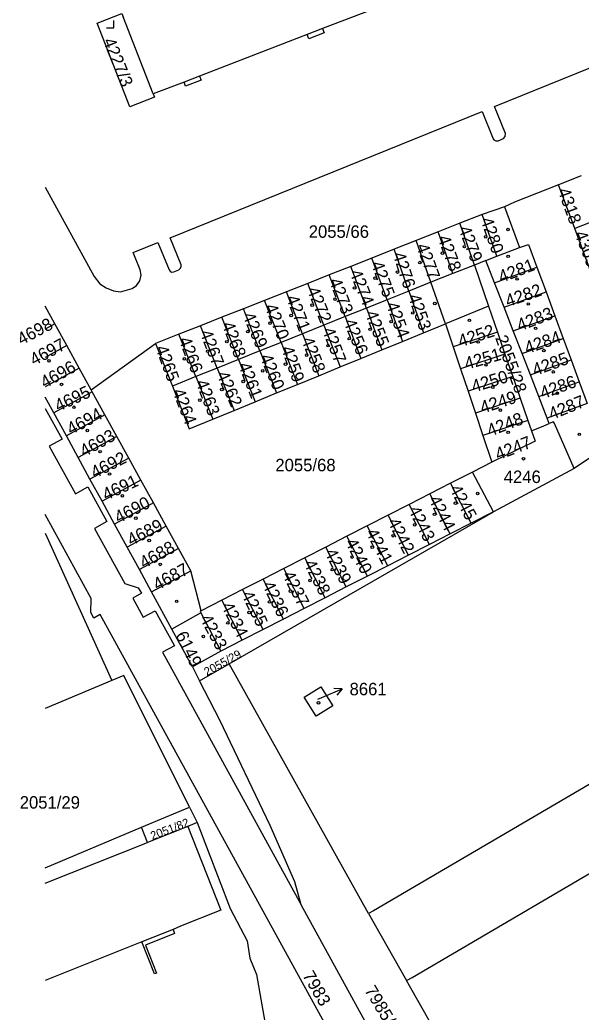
# Model space of a CAD drawing. Extents: x -564952 to -564307, y -1202373 to -1201847.
# Drawn here: x -564948.9 to -564872.3, y -1202052.1 to -1201916.7 of the extents above; entities that cross this region are included whole.
import ezdxf

# ---------------------------------------------------------------- set-up
doc = ezdxf.new("R2010")
doc.units = 0
for name, color, linetype in [('Hranice parcel', 7, 'Continuous'), ('Parcelní čísla', 7, 'Continuous'), ('Pop  PČ popisy', 7, 'Continuous'), ('Vnitřní kresba', 7, 'Continuous'), ('Značky budov', 7, 'Continuous'), ('Značky kultur', 7, 'Continuous')]:
    doc.layers.add(name, color=color, linetype=linetype)

msp = doc.modelspace()

# ---------------------------------------------------------------- linework, layer by layer
at = {"layer": 'Hranice parcel'}
for p, q in [((-564930.69, -1201926.82), (-564934.81, -1201916.29)), ((-564872.31, -1201938.01), (-564875.4, -1201939.21)), ((-564873.18, -1201945.18), (-564875.4, -1201939.21)), ((-564882.78, -1201942.21), (-564885.84, -1201943.28)), ((-564882.78, -1201942.21), (-564880.74, -1201947.76)), ((-564885.84, -1201943.28), (-564888.86, -1201944.47)), ((-564883.83, -1201948.97), (-564885.84, -1201943.28)), ((-564870.03, -1201943.94), (-564873.18, -1201945.18)), ((-564891.84, -1201945.65), (-564894.82, -1201946.82)), ((-564888.86, -1201944.47), (-564891.84, -1201945.65)), ((-564889.83, -1201951.33), (-564891.84, -1201945.65)), ((-564886.86, -1201950.16), (-564888.86, -1201944.47)), ((-564894.82, -1201946.82), (-564897.84, -1201948.02)), ((-564892.81, -1201952.5), (-564894.82, -1201946.82)), ((-564897.84, -1201948.02), (-564900.86, -1201949.21)), ((-564895.83, -1201953.72), (-564897.84, -1201948.02)), ((-564883.83, -1201948.97), (-564880.74, -1201947.76)), ((-564900.86, -1201949.21), (-564903.74, -1201950.35)), ((-564898.78, -1201954.9), (-564900.86, -1201949.21)), ((-564885.3, -1201949.55), (-564886.86, -1201950.16)), ((-564885.3, -1201949.55), (-564883.83, -1201948.97)), ((-564884.12, -1201952.6), (-564885.3, -1201949.55)), ((-564903.74, -1201950.35), (-564906.67, -1201951.51)), ((-564901.62, -1201956.04), (-564903.74, -1201950.35)), ((-564886.86, -1201950.16), (-564889.83, -1201951.33)), ((-564886.86, -1201950.16), (-564884.94, -1201955.77)), ((-564884.12, -1201952.6), (-564878.35, -1201950.46)), ((-564878.35, -1201950.46), (-564877.1, -1201953.83)), ((-564906.67, -1201951.51), (-564909.6, -1201952.66)), ((-564904.52, -1201957.2), (-564906.67, -1201951.51)), ((-564892.81, -1201952.5), (-564895.83, -1201953.72)), ((-564889.83, -1201951.33), (-564892.81, -1201952.5)), ((-564912.53, -1201953.82), (-564915.51, -1201954.99)), ((-564909.6, -1201952.66), (-564912.53, -1201953.82)), ((-564910.32, -1201959.53), (-564912.53, -1201953.82)), ((-564907.41, -1201958.36), (-564909.6, -1201952.66)), ((-564895.83, -1201953.72), (-564898.78, -1201954.9)), ((-564895.83, -1201953.72), (-564893.83, -1201959.41)), ((-564882.83, -1201955.93), (-564884.12, -1201952.6)), ((-564882.83, -1201955.93), (-564877.1, -1201953.83)), ((-564877.1, -1201953.83), (-564875.91, -1201957.07)), ((-564915.51, -1201954.99), (-564918.39, -1201956.13)), ((-564913.26, -1201960.71), (-564915.51, -1201954.99)), ((-564898.78, -1201954.9), (-564901.62, -1201956.04)), ((-564898.78, -1201954.9), (-564896.7, -1201960.58)), ((-564944.12, -1201958.18), (-564945.44, -1201955.78)), ((-564918.39, -1201956.13), (-564921.32, -1201957.29)), ((-564916.13, -1201961.87), (-564918.39, -1201956.13)), ((-564901.62, -1201956.04), (-564904.52, -1201957.2)), ((-564901.62, -1201956.04), (-564899.5, -1201961.73)), ((-564884.94, -1201955.77), (-564890.81, -1201958.17)), ((-564884.94, -1201955.77), (-564883.73, -1201959.31)), ((-564881.58, -1201959.15), (-564882.83, -1201955.93)), ((-564921.32, -1201957.29), (-564924.25, -1201958.45)), ((-564919.05, -1201963.04), (-564921.32, -1201957.29)), ((-564904.52, -1201957.2), (-564907.41, -1201958.36)), ((-564904.52, -1201957.2), (-564902.36, -1201962.9)), ((-564881.58, -1201959.15), (-564875.91, -1201957.07)), ((-564875.91, -1201957.07), (-564874.77, -1201960.17)), ((-564944.12, -1201958.18), (-564945.44, -1201958.91)), ((-564942.49, -1201961.14), (-564944.12, -1201958.18)), ((-564924.25, -1201958.45), (-564927.18, -1201959.6)), ((-564921.95, -1201964.21), (-564924.25, -1201958.45)), ((-564907.41, -1201958.36), (-564910.32, -1201959.53)), ((-564907.41, -1201958.36), (-564905.21, -1201964.06)), ((-564893.83, -1201959.41), (-564890.81, -1201958.17)), ((-564890.81, -1201958.17), (-564889.76, -1201961.32)), ((-564880.38, -1201962.23), (-564881.58, -1201959.15)), ((-564927.18, -1201959.6), (-564930.39, -1201960.87)), ((-564924.87, -1201965.38), (-564927.18, -1201959.6)), ((-564910.32, -1201959.53), (-564913.26, -1201960.71)), ((-564910.32, -1201959.53), (-564908.11, -1201965.25)), ((-564899.5, -1201961.73), (-564896.7, -1201960.58)), ((-564896.7, -1201960.58), (-564893.83, -1201959.41)), ((-564883.73, -1201959.31), (-564889.76, -1201961.32)), ((-564883.73, -1201959.31), (-564882.71, -1201962.3)), ((-564880.38, -1201962.23), (-564874.77, -1201960.17)), ((-564874.77, -1201960.17), (-564873.7, -1201963.08)), ((-564942.49, -1201961.14), (-564945.44, -1201962.77)), ((-564940.79, -1201964.23), (-564942.49, -1201961.14)), ((-564939.17, -1201967.16), (-564930.39, -1201960.87)), ((-564930.39, -1201960.87), (-564928.08, -1201966.67)), ((-564916.13, -1201961.87), (-564919.05, -1201963.04)), ((-564913.26, -1201960.71), (-564916.13, -1201961.87)), ((-564916.13, -1201961.87), (-564913.87, -1201967.61)), ((-564913.26, -1201960.71), (-564911, -1201966.44)), ((-564902.36, -1201962.9), (-564899.5, -1201961.73)), ((-564889.76, -1201961.32), (-564888.76, -1201964.32)), ((-564919.05, -1201963.04), (-564921.95, -1201964.21)), ((-564919.05, -1201963.04), (-564916.78, -1201968.8)), ((-564905.21, -1201964.06), (-564902.36, -1201962.9)), ((-564882.71, -1201962.3), (-564888.76, -1201964.32)), ((-564882.71, -1201962.3), (-564881.66, -1201965.35)), ((-564879.25, -1201965.13), (-564880.38, -1201962.23)), ((-564879.25, -1201965.13), (-564873.7, -1201963.08)), ((-564873.7, -1201963.08), (-564872.59, -1201966.08)), ((-564940.79, -1201964.23), (-564945.44, -1201966.79)), ((-564939.17, -1201967.16), (-564940.79, -1201964.23)), ((-564921.95, -1201964.21), (-564924.87, -1201965.38)), ((-564921.95, -1201964.21), (-564919.65, -1201969.98)), ((-564908.11, -1201965.25), (-564905.21, -1201964.06)), ((-564888.76, -1201964.32), (-564887.74, -1201967.37)), ((-564924.87, -1201965.38), (-564928.08, -1201966.67)), ((-564924.87, -1201965.38), (-564922.55, -1201971.16)), ((-564911, -1201966.44), (-564908.11, -1201965.25)), ((-564881.66, -1201965.35), (-564887.74, -1201967.37)), ((-564881.66, -1201965.35), (-564880.63, -1201968.34)), ((-564878.1, -1201968.11), (-564879.25, -1201965.13)), ((-564939.01, -1201967.45), (-564939.17, -1201967.16)), ((-564913.87, -1201967.61), (-564911, -1201966.44)), ((-564887.74, -1201967.37), (-564886.74, -1201970.38)), ((-564878.1, -1201968.11), (-564872.59, -1201966.08)), ((-564872.59, -1201966.08), (-564871.5, -1201969.04)), ((-564944.25, -1201970.33), (-564945.44, -1201968.16)), ((-564939.01, -1201967.45), (-564944.25, -1201970.33)), ((-564937.28, -1201970.59), (-564939.01, -1201967.45)), ((-564916.78, -1201968.8), (-564913.87, -1201967.61)), ((-564880.63, -1201968.34), (-564886.74, -1201970.38)), ((-564880.63, -1201968.34), (-564879.59, -1201971.35)), ((-564876.96, -1201971.05), (-564878.1, -1201968.11)), ((-564922.55, -1201971.16), (-564919.65, -1201969.98)), ((-564919.65, -1201969.98), (-564916.78, -1201968.8)), ((-564871.5, -1201969.04), (-564876.96, -1201971.05)), ((-564942.54, -1201973.47), (-564944.25, -1201970.33)), ((-564937.28, -1201970.59), (-564942.54, -1201973.47)), ((-564935.65, -1201973.56), (-564937.28, -1201970.59)), ((-564886.74, -1201970.38), (-564885.73, -1201973.4)), ((-564879.59, -1201971.35), (-564885.73, -1201973.4)), ((-564879.59, -1201971.35), (-564879.09, -1201972.79)), ((-564940.92, -1201976.43), (-564942.54, -1201973.47)), ((-564935.65, -1201973.56), (-564940.92, -1201976.43)), ((-564934.03, -1201976.49), (-564935.65, -1201973.56)), ((-564885.73, -1201973.4), (-564884.51, -1201977.05)), ((-564939.32, -1201979.36), (-564940.92, -1201976.43)), ((-564934.03, -1201976.49), (-564939.32, -1201979.36)), ((-564932.37, -1201979.51), (-564934.03, -1201976.49)), ((-564884.51, -1201977.05), (-564887.14, -1201978.39)), ((-564937.67, -1201982.37), (-564939.32, -1201979.36)), ((-564932.37, -1201979.51), (-564937.67, -1201982.37)), ((-564930.66, -1201982.6), (-564932.37, -1201979.51)), ((-564887.14, -1201978.39), (-564890.13, -1201979.92)), ((-564884.28, -1201983.8), (-564887.14, -1201978.39)), ((-564890.13, -1201979.92), (-564892.98, -1201981.38)), ((-564887.34, -1201985.37), (-564890.13, -1201979.92)), ((-564892.98, -1201981.38), (-564895.78, -1201982.81)), ((-564890.2, -1201986.83), (-564892.98, -1201981.38)), ((-564935.97, -1201985.49), (-564937.67, -1201982.37)), ((-564930.66, -1201982.6), (-564935.97, -1201985.49)), ((-564928.92, -1201985.76), (-564930.66, -1201982.6)), ((-564895.78, -1201982.81), (-564898.65, -1201984.28)), ((-564892.99, -1201988.26), (-564895.78, -1201982.81)), ((-564920.35, -1202004.55), (-564884.28, -1201983.8)), ((-564898.65, -1201984.28), (-564901.49, -1201985.73)), ((-564895.87, -1201989.73), (-564898.65, -1201984.28)), ((-564884.28, -1201983.8), (-564887.34, -1201985.37)), ((-564934.26, -1201988.62), (-564935.97, -1201985.49)), ((-564928.92, -1201985.76), (-564934.26, -1201988.62)), ((-564927.23, -1201988.84), (-564928.92, -1201985.76)), ((-564901.49, -1201985.73), (-564904.28, -1201987.15)), ((-564898.71, -1201991.18), (-564901.49, -1201985.73)), ((-564887.34, -1201985.37), (-564890.2, -1201986.83)), ((-564945.44, -1201986.74), (-564936.35, -1202006.83)), ((-564904.28, -1201987.15), (-564907.15, -1201988.63)), ((-564901.47, -1201992.59), (-564904.28, -1201987.15)), ((-564890.2, -1201986.83), (-564892.99, -1201988.26)), ((-564932.58, -1201991.7), (-564934.26, -1201988.62)), ((-564927.23, -1201988.84), (-564932.58, -1201991.7)), ((-564925.56, -1201991.86), (-564927.23, -1201988.84)), ((-564907.15, -1201988.63), (-564910.03, -1201990.1)), ((-564904.37, -1201994.07), (-564907.15, -1201988.63)), ((-564892.99, -1201988.26), (-564895.87, -1201989.73)), ((-564910.03, -1201990.1), (-564912.87, -1201991.55)), ((-564907.25, -1201995.54), (-564910.03, -1201990.1)), ((-564895.87, -1201989.73), (-564898.71, -1201991.18)), ((-564930.93, -1201994.72), (-564932.58, -1201991.7)), ((-564912.87, -1201991.55), (-564915.7, -1201993)), ((-564910.08, -1201996.99), (-564912.87, -1201991.55)), ((-564898.71, -1201991.18), (-564901.47, -1201992.59)), ((-564930.93, -1201994.72), (-564925.56, -1201991.86)), ((-564924.16, -1201997.32), (-564925.56, -1201991.86)), ((-564915.7, -1201993), (-564918.49, -1201994.42)), ((-564912.93, -1201998.45), (-564915.7, -1201993)), ((-564901.47, -1201992.59), (-564904.37, -1201994.07)), ((-564918.49, -1201994.42), (-564921.32, -1201995.87)), ((-564915.7, -1201999.87), (-564918.49, -1201994.42)), ((-564904.37, -1201994.07), (-564907.25, -1201995.54)), ((-564907.25, -1201995.54), (-564910.08, -1201996.99)), ((-564921.32, -1201995.87), (-564924.16, -1201997.32)), ((-564918.54, -1202001.32), (-564921.32, -1201995.87)), ((-564910.08, -1201996.99), (-564912.93, -1201998.45)), ((-564907.33, -1202053.49), (-564937.93, -1201997.84)), ((-564912.93, -1201998.45), (-564915.7, -1201999.87)), ((-564915.7, -1201999.87), (-564918.54, -1202001.32)), ((-564918.54, -1202001.32), (-564921.45, -1202002.81)), ((-564929.44, -1202002.95), (-564910.5, -1202037.44)), ((-564921.45, -1202002.81), (-564925.31, -1202004.98)), ((-564925.31, -1202004.98), (-564924.36, -1202006.85)), ((-564924.36, -1202006.85), (-564920.35, -1202004.55)), ((-564901.31, -1202038.62), (-564920.35, -1202004.55)), ((-564936.35, -1202006.83), (-564945.44, -1202010.66)), ((-564921.61, -1202012.25), (-564924.36, -1202006.85)), ((-564932.27, -1202026.82), (-564925.74, -1202024.08)), ((-564925.74, -1202024.08), (-564924.68, -1202026.21)), ((-564945.44, -1202032.36), (-564932.27, -1202026.82)), ((-564931.46, -1202028.91), (-564932.27, -1202026.82)), ((-564925.98, -1202026.73), (-564931.46, -1202028.91)), ((-564924.68, -1202026.21), (-564925.98, -1202026.73)), ((-564910.5, -1202037.44), (-564911.38, -1202034.28)), ((-564890.53, -1202073.8), (-564910.5, -1202037.44)), ((-564900.66, -1202038.24), (-564901.31, -1202038.62)), ((-564901.31, -1202038.62), (-564896.13, -1202047.75)), ((-564896.13, -1202047.75), (-564895.38, -1202047.31))]:
    msp.add_line(p, q, dxfattribs=at)
for points in [[(-564896.69, -1201913.72), (-564907.6, -1201917.92), (-564907.38, -1201918.49), (-564909.48, -1201919.31), (-564909.7, -1201918.73), (-564913.71, -1201920.28), (-564924.39, -1201924.39), (-564924.16, -1201924.97), (-564926.27, -1201925.78), (-564926.49, -1201925.2), (-564930.69, -1201926.82)], [(-564945.44, -1201939.52), (-564938.76, -1201951.71), (-564937.99, -1201952.71), (-564937.12, -1201953.29), (-564936.13, -1201953.66), (-564935.14, -1201953.8), (-564933.55, -1201953.37), (-564932.96, -1201952.94), (-564932.5, -1201952.33), (-564932.35, -1201951.55), (-564932.48, -1201950.82), (-564933.42, -1201948.47), (-564930.04, -1201947.09), (-564928.52, -1201950.82), (-564928.4, -1201950.99), (-564928.19, -1201951.14), (-564927.89, -1201951.1), (-564927.18, -1201950.81), (-564926.96, -1201950.61), (-564926.86, -1201950.34), (-564926.9, -1201950.15), (-564928.37, -1201946.43), (-564885.83, -1201929.22), (-564884.32, -1201932.93), (-564884.21, -1201933.08), (-564883.97, -1201933.22), (-564883.66, -1201933.21), (-564882.92, -1201932.91), (-564882.69, -1201932.64), (-564882.65, -1201932.23), (-564884.14, -1201928.55), (-564852.58, -1201915.77)], [(-564930.69, -1201926.82), (-564930.52, -1201927.26), (-564933.89, -1201928.57), (-564938.33, -1201917.16), (-564934.98, -1201915.86), (-564934.81, -1201916.29)], [(-564875.4, -1201939.21), (-564881.39, -1201941.61), (-564882.78, -1201942.21)], [(-564867.83, -1201949.67), (-564871.04, -1201950.95), (-564873.18, -1201945.18)], [(-564880.74, -1201947.76), (-564879.49, -1201947.36), (-564878.35, -1201950.46)], [(-564779.51, -1201950.78), (-564772.34, -1201963.08), (-564900.66, -1202038.24)], [(-564928.08, -1201966.67), (-564925.77, -1201972.48), (-564922.55, -1201971.16)], [(-564945.44, -1201969.73), (-564943.13, -1201973.9), (-564944.9, -1201974.88), (-564941.31, -1201981.37), (-564939.59, -1201980.42), (-564937, -1201985.15), (-564938.7, -1201986.1), (-564934.55, -1201993.61), (-564932.76, -1201994.17), (-564932.3, -1201994.93), (-564933.45, -1201995.59), (-564932.06, -1201998.2), (-564930.43, -1201997.3), (-564927.81, -1202002.08), (-564929.44, -1202002.95)], [(-564879.09, -1201972.79), (-564877.42, -1201972.1), (-564876.67, -1201971.79), (-564876.96, -1201971.05)], [(-564879.09, -1201972.79), (-564878.61, -1201974.17), (-564878.87, -1201974.3), (-564884.16, -1201976.87), (-564884.51, -1201977.05)], [(-564868.52, -1201974.75), (-564873.28, -1201977.89), (-564884.28, -1201983.8)], [(-564939.14, -1201995.62), (-564945.44, -1201984.18)], [(-564937.93, -1201997.84), (-564938.79, -1201998.31), (-564939.22, -1201997.55), (-564939.14, -1201995.62)], [(-564925.31, -1202004.98), (-564928.13, -1201999.83), (-564930.93, -1201994.72)], [(-564924.16, -1201997.32), (-564924.29, -1201997.39), (-564924.19, -1201997.59), (-564921.45, -1202002.81)], [(-564925.74, -1202024.08), (-564934.68, -1202006.12), (-564936.35, -1202006.83)], [(-564906.21, -1202010.26), (-564908.47, -1202011.67), (-564910.1, -1202009.09), (-564907.84, -1202007.68), (-564906.21, -1202010.26)], [(-564911.38, -1202034.28), (-564914.76, -1202026.6), (-564921.61, -1202012.25)], [(-564895.38, -1202047.31), (-564863.11, -1202028.42), (-564854.46, -1202023.35), (-564835.41, -1202055.88), (-564874.17, -1202078.58)], [(-564925.98, -1202026.73), (-564921.46, -1202038.16), (-564926.95, -1202040.34), (-564927.99, -1202040.76), (-564927.77, -1202041.31), (-564931.76, -1202042.91), (-564930.24, -1202046.72), (-564930.52, -1202046.83), (-564932.26, -1202042.46), (-564945.44, -1202047.72)], [(-564924.68, -1202026.21), (-564920.18, -1202037.93), (-564917.87, -1202042.31), (-564917.51, -1202044.68), (-564916.61, -1202046.93), (-564913.69, -1202063.48), (-564912.83, -1202087.57), (-564914.9, -1202104.2)], [(-564945.44, -1202034.48), (-564931.46, -1202028.91)], [(-564875.54, -1202079.38), (-564878.48, -1202078.86), (-564896.13, -1202047.75)]]:
    msp.add_lwpolyline(points, dxfattribs=at)
at = {"layer": 'Pop  PČ popisy'}
for p, q in [((-564907.68, -1202009.15), (-564904.92, -1202007.98)), ((-564904.92, -1202007.98), (-564906.04, -1202007.91)), ((-564904.92, -1202007.98), (-564905.64, -1202008.83)), ((-564908.22, -1202009.38), (-564907.68, -1202009.15))]:
    msp.add_line(p, q, dxfattribs=at)
at = {"layer": 'Vnitřní kresba'}
for p, q in [((-564907.6, -1201917.92), (-564909.7, -1201918.73)), ((-564924.39, -1201924.39), (-564926.49, -1201925.2)), ((-564890.81, -1201958.17), (-564892.81, -1201952.5)), ((-564876.07, -1201971.55), (-564876.67, -1201971.79)), ((-564875.97, -1201971.78), (-564876.07, -1201971.55)), ((-564873.28, -1201977.89), (-564875.97, -1201971.78)), ((-564924.19, -1201997.59), (-564928.13, -1201999.83)), ((-564927.99, -1202040.76), (-564932.26, -1202042.46))]:
    msp.add_line(p, q, dxfattribs=at)
at = {"layer": 'Značky budov'}
for centre in [(-564882.29, -1201945.31), (-564885.34, -1201946.31), (-564891.24, -1201948.55), (-564888.25, -1201947.66), (-564894.31, -1201949.83), (-564882.27, -1201948.98), (-564897.36, -1201951.12), (-564900.43, -1201951.95), (-564881.06, -1201952.06), (-564903.23, -1201953.29), (-564905.9, -1201954.82), (-564892.27, -1201955.41), (-564909.01, -1201955.63), (-564895.3, -1201956.7), (-564879.53, -1201955.47), (-564914.76, -1201958.08), (-564911.88, -1201957.04), (-564898.23, -1201957.88), (-564887.56, -1201957.7), (-564917.79, -1201959.24), (-564901.11, -1201958.93), (-564878.53, -1201958.8), (-564920.65, -1201960.61), (-564903.95, -1201960.2), (-564886.38, -1201960.65), (-564923.27, -1201961.91), (-564906.84, -1201961.15), (-564877.41, -1201961.83), (-564944.9, -1201963.23), (-564926.44, -1201962.95), (-564909.76, -1201962.46), (-564915.76, -1201964.59), (-564912.65, -1201963.68), (-564885.3, -1201963.79), (-564876.12, -1201964.74), (-564918.41, -1201966.04), (-564943.21, -1201966.44), (-564921.34, -1201967.14), (-564884.38, -1201966.81), (-564924.32, -1201968.59), (-564875.58, -1201967.65), (-564941.5, -1201969.56), (-564883.34, -1201969.96), (-564939.68, -1201972.72), (-564882.27, -1201972.98), (-564872.57, -1201973.25), (-564937.94, -1201975.62), (-564880.19, -1201976.58), (-564936.64, -1201978.66), (-564934.9, -1201981.63), (-564886.44, -1201981.32), (-564889.45, -1201982.63), (-564933.06, -1201984.68), (-564892.32, -1201984.16), (-564895.03, -1201985.6), (-564931.25, -1201987.73), (-564897.98, -1201987.08), (-564900.81, -1201988.63), (-564903.57, -1201989.99), (-564929.73, -1201990.99), (-564906.27, -1201991.7), (-564909.3, -1201993.18), (-564911.96, -1201994.63), (-564927.49, -1201996.03), (-564914.82, -1201996.11), (-564917.6, -1201997.55), (-564920.5, -1201998.97), (-564923.85, -1202000.83), (-564908.14, -1202009.87)]:
    msp.add_circle(centre, 0.175, dxfattribs=at)
at = {"layer": 'Značky kultur'}
for p, q in [((-564936.07, -1201917.8), (-564936.07, -1201916.8)), ((-564937.07, -1201917.8), (-564936.07, -1201917.8))]:
    msp.add_line(p, q, dxfattribs=at)

# ---------------------------------------------------------------- texts
at = {"layer": 'Parcelní čísla'}
for s, height, rotation, p in [('4227/3', 1.7, 292, (-564937.56, -1201919.58)), ('4318', 1.7, 290, (-564875.54, -1201939.99)), ('4280', 1.7, 289, (-564886.06, -1201943.98)), ('4279', 1.7, 291, (-564889.09, -1201945.2)), ('4305', 1.7, 291, (-564873.25, -1201945.87)), ('4278', 1.7, 290, (-564891.92, -1201946.44)), ('4277', 1.7, 290, (-564894.83, -1201947.56)), ('4276', 1.7, 288, (-564898.03, -1201948.7)), ('4281', 1.7, 21, (-564883.22, -1201952.62)), ('4274', 1.7, 292, (-564903.95, -1201951.17)), ('4275', 1.7, 290, (-564900.99, -1201949.98)), ('4273', 1.7, 291, (-564906.73, -1201952.31)), ('4272', 1.7, 292, (-564909.75, -1201953.52)), ('4282', 1.7, 19, (-564882.32, -1201955.91)), ('4271', 1.7, 291, (-564912.58, -1201954.63)), ('4253', 1.7, 289, (-564895.95, -1201954.44)), ('4270', 1.7, 292, (-564915.52, -1201955.83)), ('4255', 1.7, 291, (-564901.83, -1201956.73)), ('4254', 1.7, 290, (-564898.95, -1201955.54)), ('4283', 1.7, 21, (-564880.71, -1201959.23)), ('4698', 1.7, 28, (-564948.67, -1201961.14)), ('4269', 1.7, 293, (-564918.54, -1201957.03)), ('4256', 1.7, 292, (-564904.77, -1201957.88)), ('4267', 1.7, 291, (-564924.36, -1201959.37)), ('4268', 1.7, 291, (-564921.35, -1201958.25)), ('4257', 1.7, 291, (-564907.68, -1201959.02)), ('4252', 1.7, 18, (-564888.79, -1201961.38)), ('4284', 1.7, 19, (-564879.7, -1201962.31)), ('4697', 1.7, 28, (-564946.95, -1201963.94)), ('4266', 1.7, 291, (-564927.24, -1201960.33)), ('4258', 1.7, 291, (-564910.52, -1201960.33)), ('2055/28', 1.7, 290, (-564884.07, -1201960.08)), ('4265', 1.7, 290, (-564930.4, -1201961.46)), ('4259', 1.7, 289, (-564913.25, -1201961.52)), ('4251', 1.7, 16, (-564887.96, -1201964.46)), ('4696', 1.7, 29, (-564945.49, -1201967.03)), ('4260', 1.7, 292, (-564916.16, -1201962.68)), ('4285', 1.7, 20, (-564878.61, -1201965.31)), ('4261', 1.7, 291, (-564919.11, -1201963.8)), ('4250', 1.7, 17, (-564886.98, -1201967.57)), ('4263', 1.7, 291, (-564924.93, -1201966.15)), ('4262', 1.7, 294, (-564922.08, -1201965.07)), ('4286', 1.7, 20, (-564877.57, -1201968.46)), ('4695', 1.7, 25, (-564943.65, -1201970.21)), ('4264', 1.7, 291, (-564928.09, -1201967.38)), ('4249', 1.7, 18, (-564885.79, -1201970.45)), ('4287', 1.7, 22, (-564876.35, -1201971.32)), ('4694', 1.7, 28, (-564941.92, -1201973.38)), ('4248', 1.7, 21, (-564884.78, -1201973.59)), ('4693', 1.7, 29, (-564940.12, -1201976.39)), ('4247', 1.7, 21, (-564883.66, -1201976.82)), ('4692', 1.7, 27, (-564938.68, -1201979.32)), ('4691', 1.7, 25, (-564937.14, -1201982.33)), ('4245', 1.7, 298, (-564890.33, -1201980.66)), ('4690', 1.7, 27, (-564935.44, -1201985.44)), ('4244', 1.7, 297, (-564893.18, -1201982.11)), ('4243', 1.7, 297, (-564895.96, -1201983.53)), ('4689', 1.7, 27, (-564933.71, -1201988.51)), ('4242', 1.7, 297, (-564898.76, -1201985.18)), ('4241', 1.7, 297, (-564901.73, -1201986.61)), ('4688', 1.7, 29, (-564931.97, -1201991.63)), ('4240', 1.7, 297, (-564904.54, -1201987.96)), ('4239', 1.7, 297, (-564907.36, -1201989.34)), ('4687', 1.7, 28, (-564930.15, -1201994.59)), ('4238', 1.7, 297, (-564910.22, -1201990.85)), ('4237', 1.7, 297, (-564913.13, -1201992.4)), ('4236', 1.7, 296, (-564915.87, -1201993.76)), ('4235', 1.7, 296, (-564918.71, -1201995.08)), ('4234', 1.7, 297, (-564921.45, -1201996.65)), ('4233', 1.7, 298, (-564924.37, -1201998.35)), ('6149', 1.7, 296, (-564927.7, -1202000.61)), ('2055/29', 1.14, 29, (-564923.37, -1202006.24)), ('2051/82', 1.14, 21, (-564930.81, -1202028.6)), ('7983', 1.7, 300, (-564910.38, -1202047.03)), ('7985/2', 1.7, 301, (-564901.93, -1202049.07))]:
    msp.add_text(s, height=height, rotation=rotation, dxfattribs=at).set_placement(p)
for s, p in [('2055/66', (-564909.48, -1201946.45)), ('2055/68', (-564914.03, -1201978.29)), ('4246', (-564882.88, -1201979.89)), ('8661', (-564903.91, -1202008.84)), ('2051/29', (-564948.9, -1202024.3))]:
    msp.add_text(s, height=1.7, dxfattribs=at).set_placement(p)

doc.saveas('drawing.dxf')
